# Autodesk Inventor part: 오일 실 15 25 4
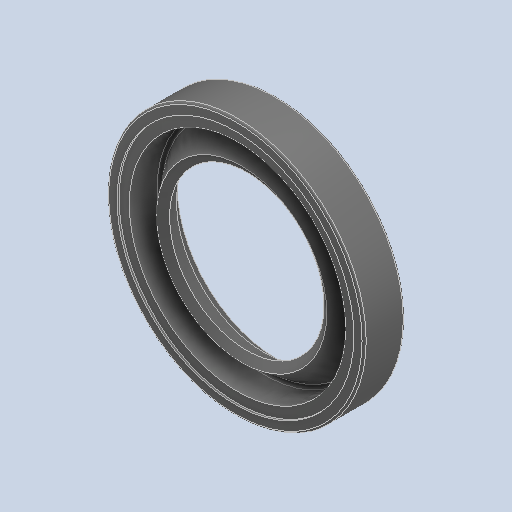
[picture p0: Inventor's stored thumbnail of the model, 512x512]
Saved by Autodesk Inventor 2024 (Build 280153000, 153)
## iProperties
Created: 2025-10
Part Number: 오일 실 15 25 4
Material: 고무
Description: 오일 실 - 비스프링, 조립 GA
Document SubType Name: Modeling
Designer: EDU03
Density: 0.93 g/cm^3
Appearance: 기본값
Author: jhkim
Sending System: Autodesk Inventor 2026
Preprocessor: ST-DEVELOPER v20.1
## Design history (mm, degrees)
feature "Solid1"
node "솔리드1"
